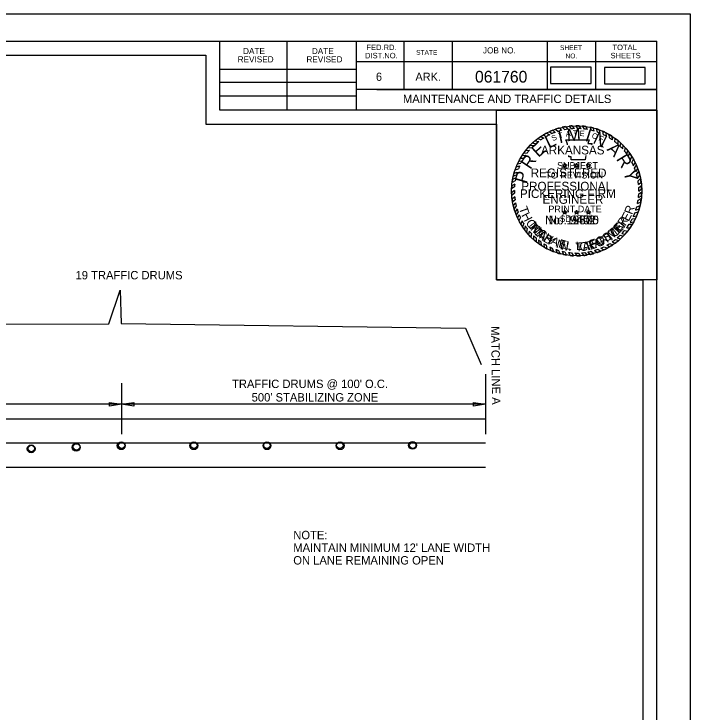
# Model space of a CAD drawing. Extents: x -500 to 213, y 382723 to 382830.
# Drawn here: x -198.06 to -149.61, y 382779.8 to 382829.8 of the extents above; entities that cross this region are included whole.
import ezdxf

# ---------------------------------------------------------------- set-up
doc = ezdxf.new("R2010")
doc.units = 0
for name, color, linetype in [('Default', 7, 'Continuous'), ('R_Border', 7, 'Continuous'), ('R_Border Notes', 7, 'Continuous'), ('R_No Plot', 7, 'Continuous'), ('STAMP_PE_CRAFTON', 7, 'Continuous'), ('STAMP_PE_FOSTER', 7, 'Continuous'), ('STAMP_PE_SEAL-INFO', 7, 'Continuous'), ('STAMP_PE_TAEGTMEYER', 7, 'Continuous'), ('STAMP_PE_TXT', 7, 'Continuous'), ('STAMP_PRELIMINARY', 7, 'Continuous')]:
    doc.layers.add(name, color=color, linetype=linetype)

msp = doc.modelspace()

# ---------------------------------------------------------------- linework, layer by layer
at = {"layer": 'Default'}
for p, q in [((-164.267, 382804.001), (-164.267, 382799.695)), ((-190.345, 382803.352), (-190.345, 382799.695)), ((-191.214, 382801.718), (-191.214, 382801.979)), ((-191.214, 382801.979), (-190.345, 382801.848)), ((-190.345, 382801.848), (-189.476, 382801.979)), ((-189.476, 382801.979), (-189.476, 382801.718)), ((-165.137, 382801.718), (-165.137, 382801.979)), ((-165.137, 382801.979), (-164.267, 382801.848)), ((-190.345, 382801.848), (-235.546, 382801.848)), ((-190.345, 382801.848), (-191.214, 382801.718)), ((-164.267, 382801.848), (-190.345, 382801.848)), ((-189.476, 382801.718), (-190.345, 382801.848)), ((-164.267, 382801.848), (-165.137, 382801.718)), ((-235.546, 382800.808), (-164.267, 382800.808)), ((-235.546, 382799.07), (-164.267, 382799.07)), ((-235.546, 382797.331), (-164.267, 382797.331))]:
    msp.add_line(p, q, dxfattribs=at)
for points in [[(-159.612, 382824.821), (-156.695, 382824.821), (-156.695, 382825.976), (-159.612, 382825.976)], [(-155.736, 382824.804), (-152.819, 382824.804), (-152.819, 382825.959), (-155.736, 382825.959)]]:
    msp.add_lwpolyline(points, close=True, dxfattribs=at)
msp.add_lwpolyline([(-235.059, 382804.933), (-233.084, 382807.551), (-191.258, 382807.599), (-190.452, 382810.018), (-190.38, 382807.634), (-165.711, 382807.3), (-164.57, 382804.702)], dxfattribs=at)
for centre, radius in [((-196.824, 382798.651), 0.281), ((-196.812, 382798.675), 0.229), ((-193.598, 382798.762), 0.281), ((-193.575, 382798.789), 0.229), ((-190.373, 382798.872), 0.281), ((-190.35, 382798.905), 0.229), ((-190.338, 382798.904), 0.229), ((-185.169, 382798.872), 0.281), ((-185.161, 382798.902), 0.229), ((-179.926, 382798.873), 0.281), ((-179.934, 382798.902), 0.229), ((-174.684, 382798.873), 0.281), ((-174.707, 382798.902), 0.229), ((-169.497, 382798.899), 0.281), ((-169.48, 382798.902), 0.229)]:
    msp.add_circle(centre, radius, dxfattribs=at)
at = {"layer": 'R_Border'}
for p, q in [((-310.08, 382827.85), (-151.99, 382827.85)), ((-183.31, 382822.91), (-183.31, 382827.85)), ((-178.47, 382822.91), (-178.47, 382827.85)), ((-173.54, 382827.85), (-173.54, 382822.91)), ((-170.12, 382827.85), (-170.12, 382824.38)), ((-166.65, 382827.85), (-166.65, 382824.38)), ((-159.86, 382827.85), (-159.86, 382824.38)), ((-156.39, 382827.85), (-156.39, 382824.38)), ((-151.99, 382725.12), (-151.99, 382827.85)), ((-151.99, 382826.38), (-173.54, 382826.38)), ((-151.99, 382826.39), (-151.99, 382826.39)), ((-183.31, 382825.84), (-173.54, 382825.84)), ((-183.31, 382824.91), (-173.54, 382824.91)), ((-151.99, 382824.38), (-173.54, 382824.38)), ((-172.06, 382824.38), (-151.99, 382824.38)), ((-183.31, 382823.94), (-173.54, 382823.94)), ((-151.99, 382822.91), (-183.31, 382822.91))]:
    msp.add_line(p, q, dxfattribs=at)
at = {"layer": 'R_No Plot'}
for points in [[(-316.283, 382829.798), (-149.613, 382829.798), (-149.613, 382723.129), (-316.283, 382723.129)], [(-152.99, 382777.485), (-309.08, 382777.485), (-309.08, 382826.85), (-184.31, 382826.85), (-184.31, 382821.91), (-175.54, 382821.91), (-163.49, 382821.91), (-163.49, 382810.744), (-152.99, 382810.744)], [(-309.08, 382826.85), (-184.31, 382826.85), (-184.31, 382821.91), (-175.54, 382821.91), (-163.49, 382821.91), (-163.49, 382810.744), (-152.99, 382810.744), (-152.99, 382726.12), (-309.08, 382726.12)], [(-163.49, 382822.91), (-151.99, 382822.91), (-151.99, 382810.744), (-163.49, 382810.744)]]:
    msp.add_lwpolyline(points, close=True, dxfattribs=at)
at = {"layer": 'STAMP_PE_SEAL-INFO'}
for p, q in [((-159.688, 382821.366), (-159.493, 382821.229)), ((-159.434, 382821.474), (-159.287, 382821.311)), ((-159.26, 382821.538), (-159.07, 382821.385)), ((-158.964, 382821.629), (-158.821, 382821.455)), ((-158.771, 382821.678), (-158.593, 382821.506)), ((-158.529, 382821.726), (-158.38, 382821.542)), ((-158.272, 382821.763), (-158.131, 382821.571)), ((-157.904, 382821.585), (-158.06, 382821.782)), ((-157.655, 382821.588), (-157.794, 382821.793)), ((-157.426, 382821.577), (-157.555, 382821.789)), ((-157.173, 382821.552), (-157.319, 382821.774)), ((-156.96, 382821.52), (-157.089, 382821.747)), ((-156.679, 382821.46), (-156.766, 382821.69)), ((-156.478, 382821.406), (-156.558, 382821.641)), ((-156.252, 382821.333), (-156.323, 382821.573)), ((-156.043, 382821.253), (-156.115, 382821.501)), ((-155.812, 382821.15), (-155.864, 382821.399)), ((-160.531, 382820.88), (-160.303, 382820.778)), ((-160.321, 382821.013), (-160.1, 382820.912)), ((-160.127, 382821.135), (-159.911, 382821.024)), ((-159.903, 382821.261), (-159.671, 382821.148)), ((-155.59, 382821.036), (-155.633, 382821.29)), ((-155.396, 382820.922), (-155.416, 382821.172)), ((-155.179, 382820.779), (-155.194, 382821.037)), ((-154.998, 382820.646), (-154.981, 382820.889)), ((-161.059, 382820.405), (-160.787, 382820.384)), ((-160.891, 382820.566), (-160.662, 382820.497)), ((-160.719, 382820.716), (-160.455, 382820.666)), ((-158.503, 382820.777), (-156.831, 382820.777)), ((-158.443, 382820.624), (-158.503, 382820.777)), ((-158.391, 382820.475), (-158.443, 382820.624)), ((-158.387, 382820.418), (-158.391, 382820.475)), ((-156.831, 382820.777), (-156.944, 382820.531)), ((-156.944, 382820.531), (-156.627, 382820.531)), ((-156.627, 382820.531), (-156.7, 382820.418)), ((-154.775, 382820.459), (-154.765, 382820.721)), ((-154.619, 382820.313), (-154.584, 382820.563)), ((-154.439, 382820.127), (-154.406, 382820.39)), ((-161.393, 382820.027), (-161.119, 382820.038)), ((-161.22, 382820.232), (-160.959, 382820.213)), ((-154.302, 382819.968), (-154.234, 382820.204)), ((-154.14, 382819.76), (-154.073, 382820.01)), ((-161.772, 382819.469), (-161.528, 382819.48)), ((-161.649, 382819.67), (-161.391, 382819.687)), ((-161.532, 382819.842), (-161.28, 382819.839)), ((-158.291, 382819.563), (-158.304, 382819.672)), ((-158.134, 382819.563), (-158.291, 382819.563)), ((-158.134, 382819.348), (-158.134, 382819.563)), ((-157.112, 382819.517), (-157.119, 382819.348)), ((-157.073, 382819.672), (-157.112, 382819.517)), ((-154.03, 382819.602), (-153.941, 382819.834)), ((-153.876, 382819.354), (-153.785, 382819.599)), ((-153.777, 382819.17), (-153.663, 382819.392)), ((-162.074, 382818.847), (-161.822, 382818.92)), ((-161.982, 382819.063), (-161.731, 382819.115)), ((-161.888, 382819.258), (-161.639, 382819.29)), ((-157.119, 382819.348), (-158.134, 382819.348)), ((-153.661, 382818.928), (-153.548, 382819.171)), ((-153.591, 382818.76), (-153.459, 382818.977)), ((-162.227, 382818.393), (-161.989, 382818.477)), ((-162.149, 382818.644), (-161.907, 382818.712)), ((-153.493, 382818.485), (-153.358, 382818.722)), ((-153.44, 382818.303), (-153.293, 382818.529)), ((-162.097, 382818.066), (-162.33, 382817.941)), ((-162.28, 382818.189), (-162.045, 382818.285)), ((-153.373, 382818.024), (-153.214, 382818.247)), ((-153.339, 382817.834), (-153.162, 382818.01)), ((-162.188, 382817.406), (-162.399, 382817.278)), ((-162.17, 382817.618), (-162.388, 382817.478)), ((-162.14, 382817.836), (-162.363, 382817.725)), ((-153.305, 382817.579), (-153.119, 382817.747)), ((-153.289, 382817.37), (-153.094, 382817.516)), ((-162.196, 382817.159), (-162.399, 382816.991)), ((-162.193, 382816.956), (-162.389, 382816.793)), ((-153.289, 382816.908), (-153.079, 382817.047)), ((-153.283, 382817.111), (-153.08, 382817.272)), ((-162.176, 382816.708), (-162.362, 382816.53)), ((-162.15, 382816.493), (-162.327, 382816.307)), ((-153.334, 382816.461), (-153.112, 382816.571)), ((-153.308, 382816.655), (-153.091, 382816.783)), ((-162.111, 382816.264), (-162.281, 382816.08)), ((-162.064, 382816.055), (-162.221, 382815.847)), ((-153.433, 382815.985), (-153.197, 382816.086)), ((-153.379, 382816.211), (-153.152, 382816.309)), ((-162.002, 382815.831), (-162.15, 382815.622)), ((-161.932, 382815.619), (-162.073, 382815.414)), ((-161.849, 382815.406), (-161.98, 382815.195)), ((-153.574, 382815.548), (-153.332, 382815.614)), ((-153.506, 382815.738), (-153.261, 382815.838)), ((-161.763, 382815.214), (-161.877, 382814.984)), ((-161.646, 382814.985), (-161.741, 382814.74)), ((-153.897, 382814.873), (-153.647, 382814.901)), ((-153.761, 382815.123), (-153.517, 382815.157)), ((-153.681, 382815.291), (-153.437, 382815.339)), ((-161.528, 382814.784), (-161.62, 382814.548)), ((-161.426, 382814.628), (-161.481, 382814.352)), ((-161.286, 382814.433), (-161.337, 382814.167)), ((-154.153, 382814.486), (-153.901, 382814.488)), ((-153.983, 382814.733), (-153.745, 382814.73)), ((-161.134, 382814.244), (-161.177, 382813.984)), ((-160.983, 382814.075), (-161.014, 382813.814)), ((-160.822, 382813.912), (-160.837, 382813.648)), ((-154.626, 382813.943), (-154.406, 382813.874)), ((-154.499, 382814.073), (-154.26, 382814.03)), ((-154.307, 382814.289), (-154.076, 382814.249)), ((-160.649, 382813.756), (-160.651, 382813.491)), ((-160.469, 382813.609), (-160.46, 382813.347)), ((-160.3, 382813.484), (-160.282, 382813.225)), ((-155.367, 382813.359), (-155.142, 382813.261)), ((-155.195, 382813.473), (-154.975, 382813.378)), ((-154.964, 382813.645), (-154.73, 382813.572)), ((-154.829, 382813.757), (-154.593, 382813.692)), ((-160.087, 382813.343), (-160.056, 382813.087)), ((-159.912, 382813.24), (-159.866, 382812.984)), ((-159.671, 382813.115), (-159.593, 382812.855)), ((-159.485, 382813.031), (-159.398, 382812.775)), ((-159.238, 382812.935), (-159.134, 382812.684)), ((-159.034, 382812.867), (-158.921, 382812.622)), ((-156.463, 382812.862), (-156.255, 382812.713)), ((-156.217, 382812.943), (-155.996, 382812.809)), ((-156.007, 382813.025), (-155.796, 382812.895)), ((-155.778, 382813.13), (-155.536, 382813.024)), ((-155.574, 382813.237), (-155.365, 382813.12)), ((-158.78, 382812.798), (-158.674, 382812.565)), ((-158.581, 382812.755), (-158.458, 382812.526)), ((-158.331, 382812.714), (-158.211, 382812.494)), ((-158.113, 382812.691), (-157.975, 382812.476)), ((-157.87, 382812.677), (-157.719, 382812.47)), ((-157.64, 382812.676), (-157.468, 382812.478)), ((-157.381, 382812.689), (-157.218, 382812.5)), ((-157.162, 382812.713), (-156.975, 382812.533)), ((-156.939, 382812.747), (-156.745, 382812.578)), ((-156.693, 382812.8), (-156.504, 382812.637))]:
    msp.add_line(p, q, dxfattribs=at)
for radius, start, end in [(4.661, 111.3124, 114.7026), (4.661, 105.2339, 109.0352), (4.457, 104.0352, 107.3615), (4.661, 99.7525, 102.7765), (4.457, 98.258, 101.0329), (4.661, 93.9381, 96.5517), (4.457, 92.1102, 95.0367), (4.661, 87.7298, 90.6707), (4.457, 85.9628, 88.9097), (4.661, 81.9732, 84.8236), (4.457, 79.9264, 82.696), (4.661, 75.3125, 77.9426), (4.457, 73.5575, 76.2314), (4.661, 69.6061, 72.3058), (4.661, 63.1329, 66.2704), (4.661, 123.6199, 126.5906), (4.457, 121.9746, 125.11), (4.661, 117.6544, 120.8099), (4.457, 115.6869, 119.1583), (4.457, 110.3086, 113.1659), (4.457, 67.6248, 70.504), (4.457, 61.1558, 64.3784), (4.661, 56.9003, 60.0942), (4.457, 54.9238, 58.2702), (4.661, 50.3492, 53.7159), (4.661, 135.4021, 138.3031), (4.457, 133.1331, 136.2562), (4.661, 129.7326, 132.5376), (4.457, 127.5297, 130.9683), (4.457, 48.3016, 52.0395), (4.661, 44.3405, 47.3929), (4.661, 141.6056, 144.4486), (4.457, 139.301, 142.5873), (4.457, 42.2212, 45.5512), (4.457, 36.135, 39.5311), (4.661, 38.1247, 41.2316), (4.661, 147.0072, 149.899), (4.457, 145.0197, 148.2104), (4.457, 29.9032, 33.6645), (4.661, 31.9614, 35.4294), (4.661, 25.9391, 29.0125), (4.661, 152.864, 155.5189), (4.457, 156.3402, 159.2319), (4.457, 151.0315, 153.573), (4.457, 23.7732, 27.2211), (4.661, 19.9538, 23.3141), (4.661, 164.3068, 166.894), (4.661, 158.4077, 161.0701), (4.457, 162.4331, 165.0013), (4.457, 17.6802, 21.4251), (4.661, 13.8421, 17.4447), (4.661, 170.0003, 172.6878), (4.457, 167.9048, 170.9039), (4.457, 11.5444, 15.2364), (4.661, 7.5852, 10.8621), (4.661, 175.7409, 178.2066), (4.457, 173.73, 176.4734), (4.457, 5.7599, 9.0606), (4.457, 359.7329, 3.0639), (4.661, 1.7215, 4.7268), (4.661, 181.7251, 184.1626), (4.457, 179.6454, 182.2633), (4.457, 353.8632, 357.1274), (4.661, 355.7156, 358.9569), (4.661, 187.4204, 190.1927), (4.457, 185.4539, 188.234), (4.457, 348.0778, 351.3435), (4.661, 349.8305, 353.0885), (4.661, 193.0369, 195.9973), (4.457, 191.2274, 193.9858), (4.457, 341.777, 345.0925), (4.661, 343.8925, 347.035), (4.661, 198.8967, 201.6281), (4.457, 196.9675, 199.8353), (4.457, 202.7761, 205.4791), (4.457, 335.6038, 339.1858), (4.661, 337.3837, 340.9933), (4.661, 204.5479, 207.4328), (4.457, 208.7883, 211.7934), (4.457, 329.5549, 333.2076), (4.661, 331.4037, 334.9332), (4.661, 210.8636, 213.6571), (4.661, 216.6115, 219.491), (4.457, 214.1838, 217.2747), (4.457, 323.5851, 327.4407), (4.661, 325.4405, 328.9872), (4.661, 222.48, 225.3801), (4.457, 220.3909, 223.3056), (4.457, 226.2494, 229.2407), (4.457, 310.7744, 314.3161), (4.661, 312.4518, 315.6633), (4.457, 316.6531, 320.3711), (4.661, 318.2846, 321.8043), (4.661, 228.3665, 231.348), (4.457, 232.229, 234.9336), (4.457, 299.0768, 302.1724), (4.457, 304.823, 308.5143), (4.661, 306.3721, 310.208), (4.661, 234.295, 236.9452), (4.457, 238.2223, 240.8353), (4.661, 240.1977, 242.8613), (4.457, 244.3204, 246.9486), (4.661, 246.576, 249.1558), (4.457, 250.3491, 253.1216), (4.457, 286.6423, 289.9783), (4.457, 292.8745, 296.1185), (4.661, 294.6481, 298.2166), (4.661, 300.621, 303.8703), (4.661, 252.5967, 255.3252), (4.457, 256.505, 259.1192), (4.661, 258.4433, 261.1398), (4.457, 262.3783, 265.2012), (4.661, 264.1978, 267.1009), (4.457, 268.3215, 271.277), (4.661, 270.2548, 273.3361), (4.457, 274.6157, 277.4486), (4.661, 276.4239, 279.4357), (4.457, 280.3459, 283.5814), (4.661, 282.3199, 285.3702), (4.661, 288.5709, 291.9733)]:
    msp.add_arc((-157.74, 382817.132), radius, start, end, dxfattribs=at)
at = {"layer": 'STAMP_PE_TXT'}
for p, q in [((-158.65, 382818.917), (-158.749, 382818.99)), ((-158.749, 382818.99), (-158.627, 382818.99)), ((-158.688, 382818.801), (-158.65, 382818.917)), ((-158.589, 382818.873), (-158.688, 382818.801)), ((-158.627, 382818.99), (-158.589, 382819.106)), ((-158.589, 382819.106), (-158.551, 382818.99)), ((-158.489, 382818.801), (-158.589, 382818.873)), ((-158.551, 382818.99), (-158.428, 382818.99)), ((-158.428, 382818.99), (-158.527, 382818.917)), ((-158.527, 382818.917), (-158.489, 382818.801)), ((-157.801, 382818.917), (-157.9, 382818.99)), ((-157.9, 382818.99), (-157.778, 382818.99)), ((-157.839, 382818.801), (-157.801, 382818.917)), ((-157.74, 382818.873), (-157.839, 382818.801)), ((-157.778, 382818.99), (-157.74, 382819.106)), ((-157.74, 382819.106), (-157.702, 382818.99)), ((-157.64, 382818.801), (-157.74, 382818.873)), ((-157.702, 382818.99), (-157.579, 382818.99)), ((-157.579, 382818.99), (-157.678, 382818.917)), ((-157.678, 382818.917), (-157.64, 382818.801)), ((-156.952, 382818.917), (-157.051, 382818.99)), ((-157.051, 382818.99), (-156.929, 382818.99)), ((-156.99, 382818.801), (-156.952, 382818.917)), ((-156.891, 382818.873), (-156.99, 382818.801)), ((-156.929, 382818.99), (-156.891, 382819.106)), ((-156.891, 382819.106), (-156.853, 382818.99)), ((-156.792, 382818.801), (-156.891, 382818.873)), ((-156.853, 382818.99), (-156.73, 382818.99)), ((-156.73, 382818.99), (-156.829, 382818.917)), ((-156.829, 382818.917), (-156.792, 382818.801)), ((-158.65, 382815.564), (-158.749, 382815.636)), ((-158.749, 382815.636), (-158.627, 382815.636)), ((-158.688, 382815.447), (-158.65, 382815.564)), ((-158.589, 382815.519), (-158.688, 382815.447)), ((-158.627, 382815.636), (-158.589, 382815.753)), ((-158.589, 382815.753), (-158.551, 382815.636)), ((-158.489, 382815.447), (-158.589, 382815.519)), ((-158.551, 382815.636), (-158.428, 382815.636)), ((-158.428, 382815.636), (-158.527, 382815.564)), ((-158.527, 382815.564), (-158.489, 382815.447)), ((-157.801, 382815.564), (-157.9, 382815.636)), ((-157.9, 382815.636), (-157.778, 382815.636)), ((-157.839, 382815.447), (-157.801, 382815.564)), ((-157.74, 382815.519), (-157.839, 382815.447)), ((-157.778, 382815.636), (-157.74, 382815.753)), ((-157.74, 382815.753), (-157.702, 382815.636)), ((-157.64, 382815.447), (-157.74, 382815.519)), ((-157.702, 382815.636), (-157.579, 382815.636)), ((-157.579, 382815.636), (-157.678, 382815.564)), ((-157.678, 382815.564), (-157.64, 382815.447)), ((-156.952, 382815.564), (-157.051, 382815.636)), ((-157.051, 382815.636), (-156.929, 382815.636)), ((-156.99, 382815.447), (-156.952, 382815.564)), ((-156.891, 382815.519), (-156.99, 382815.447)), ((-156.929, 382815.636), (-156.891, 382815.753)), ((-156.891, 382815.753), (-156.853, 382815.636)), ((-156.792, 382815.447), (-156.891, 382815.519)), ((-156.853, 382815.636), (-156.73, 382815.636)), ((-156.73, 382815.636), (-156.829, 382815.564)), ((-156.829, 382815.564), (-156.792, 382815.447))]:
    msp.add_line(p, q, dxfattribs=at)
at = {"layer": 'STAMP_PRELIMINARY'}
msp.add_circle((-157.74, 382817.132), 4.661, dxfattribs=at)

# ---------------------------------------------------------------- texts
at = {"layer": 'Default'}
for s, p in [('19 TRAFFIC DRUMS', (-193.644, 382810.789)), ("TRAFFIC DRUMS @ 100' O.C.", (-182.431, 382803.004)), ("500' STABILIZING ZONE", (-181.027, 382802.04)), ('NOTE:', (-178.043, 382792.175)), ("MAINTAIN MINIMUM 12' LANE WIDTH", (-178.043, 382791.27)), ('ON LANE REMAINING OPEN', (-178.043, 382790.365))]:
    msp.add_text(s, height=0.6, dxfattribs=at).set_placement(p)
msp.add_text('MATCH LINE A', height=0.6, rotation=270.8059, dxfattribs=at).set_placement((-163.875, 382807.429))
at = {"layer": 'R_Border'}
for s, height, p in [('DATE', 0.4396, (-181.641, 382826.919)), ('DATE', 0.4396, (-176.711, 382826.919)), ('FED.RD.', 0.391, (-172.8, 382827.21)), ('JOB NO.', 0.4396, (-164.45, 382826.97)), ('SHEET', 0.342, (-158.93, 382827.21)), ('TOTAL', 0.391, (-155.17, 382827.21)), ('DIST.NO.', 0.391, (-172.9, 382826.62)), ('STATE', 0.342, (-169.24, 382826.87)), ('NO.', 0.342, (-158.54, 382826.62)), ('SHEETS', 0.391, (-155.31, 382826.62)), ('REVISED', 0.4396, (-182.031, 382826.329)), ('REVISED', 0.4396, (-177.101, 382826.329)), ('6', 0.586, (-172.12, 382825.01)), ('ARK.', 0.5861, (-169.29, 382825.01))]:
    msp.add_text(s, height=height, dxfattribs=at).set_placement(p)
at = {"layer": 'R_Border Notes'}
for s, height, p in [('061760', 0.84, (-165.021, 382824.883)), ('MAINTENANCE AND TRAFFIC DETAILS', 0.6, (-170.186, 382823.42))]:
    msp.add_text(s, height=height, dxfattribs=at).set_placement(p)
at = {"layer": 'STAMP_PE_CRAFTON'}
msp.add_text('No. 12370', height=0.625, dxfattribs=at).set_placement((-160.009, 382814.73))
for s, rotation, p in [('T', 310.7442, (-161.257, 382814.581)), ('N', 49.2411, (-154.598, 382814.143)), ('O', 317.6422, (-160.923, 382814.175)), ('O', 41.8391, (-155.022, 382813.752)), ('N', 324.4537, (-160.5, 382813.783)), ('Y', 331.1686, (-159.984, 382813.424)), ('F', 28.7821, (-155.909, 382813.196)), ('T', 34.1136, (-155.451, 382813.451)), ('N', 347.4752, (-158.956, 382812.966)), ('C', 6.0117, (-157.504, 382812.802)), ('R', 14.8189, (-156.956, 382812.86)), ('A', 20.5125, (-156.399, 382813.01)), ('.', 356.8926, (-158.342, 382812.828))]:
    msp.add_text(s, height=0.625, rotation=rotation, dxfattribs=at).set_placement(p)
at = {"layer": 'STAMP_PE_FOSTER'}
msp.add_text('No. 9402', height=0.625, dxfattribs=at).set_placement((-159.747, 382814.73))
for s, rotation, p in [('M', 308.339, (-161.182, 382814.643)), ('E', 46.9613, (-154.739, 382814.127)), ('R', 54.5031, (-154.378, 382814.537)), ('I', 314.1842, (-160.783, 382814.174)), ('T', 39.4194, (-155.169, 382813.752)), ('C', 319.8733, (-160.606, 382813.997)), ('H', 327.7235, (-160.141, 382813.629)), ('O', 23.719, (-156.2, 382813.173)), ('S', 31.7234, (-155.644, 382813.438)), ('A', 335.7276, (-159.651, 382813.338)), ('E', 343.5779, (-159.082, 382813.103)), ('L', 350.8115, (-158.553, 382812.964)), ('L', 1.2666, (-157.783, 382812.886)), ('F', 15.8691, (-156.722, 382813.009)), ('.', 6.8035, (-157.26, 382812.915))]:
    msp.add_text(s, height=0.6, rotation=rotation, dxfattribs=at).set_placement(p)
at = {"layer": 'STAMP_PE_TAEGTMEYER'}
for s, rotation, p in [('T', 289.646, (-161.892, 382815.887)), ('R', 69.57, (-153.767, 382815.389)), ('H', 296.7339, (-161.713, 382815.395)), ('E', 63.0984, (-154.016, 382814.898)), ('O', 303.7708, (-161.416, 382814.841)), ('Y', 53.9986, (-154.351, 382814.428)), ('M', 314.2033, (-161.089, 382814.365)), ('M', 39.3, (-155.241, 382813.581)), ('E', 46.8094, (-154.72, 382814.02)), ('A', 321.0594, (-160.608, 382813.883)), ('S', 327.8239, (-160.195, 382813.561)), ('T', 31.466, (-155.69, 382813.309)), ('N', 344.2727, (-159.246, 382813.058)), ('T', 3.0061, (-157.808, 382812.792)), ('A', 8.9826, (-157.284, 382812.82)), ('E', 17.6836, (-156.765, 382812.897)), ('G', 23.3052, (-156.24, 382813.063)), ('.', 350.6464, (-158.64, 382812.892))]:
    msp.add_text(s, height=0.625, rotation=rotation, dxfattribs=at).set_placement(p)
msp.add_text('No. 19605', height=0.625, dxfattribs=at).set_placement((-160.009, 382814.73))
at = {"layer": 'STAMP_PE_TXT'}
for s, rotation, p in [('A', 9.0679, (-158.498, 382820.996)), ('T', 1.8248, (-158.004, 382821.061)), ('E', 355.2002, (-157.549, 382821.065)), ('S', 23.5541, (-159.44, 382820.684)), ('T', 16.311, (-158.979, 382820.87)), ('O', 342.2506, (-156.686, 382820.927)), ('F', 335.0075, (-156.203, 382820.758))]:
    msp.add_text(s, height=0.391, rotation=rotation, dxfattribs=at).set_placement(p)
for s, p in [('ARKANSAS', (-160.294, 382819.737)), ('REGISTERED', (-161.031, 382818.102)), ('PROFESSIONAL', (-161.705, 382817.151)), ('ENGINEER', (-160.185, 382816.201))]:
    msp.add_text(s, height=0.625, dxfattribs=at).set_placement(p)
at = {"layer": 'STAMP_PRELIMINARY'}
for s, rotation, p in [('I', 12.5248, (-158.971, 382820.525)), ('M', 3.1074, (-158.422, 382820.68)), ('I', 342.3164, (-157.188, 382820.713)), ('L', 25.513, (-159.735, 382820.145)), ('N', 333.9382, (-156.634, 382820.576)), ('E', 42.3578, (-160.477, 382819.48)), ('A', 315.6579, (-155.617, 382820.064)), ('R', 56.2292, (-161.054, 382818.614)), ('R', 301.3831, (-154.933, 382819.407)), ('P', 73.913, (-161.329, 382817.602)), ('Y', 283.2593, (-154.389, 382818.513))]:
    msp.add_text(s, height=0.9, rotation=rotation, dxfattribs=at).set_placement(p)
for s, height, p in [('SUBJECT', 0.48, (-159.14, 382818.706)), ('TO REVISION', 0.48, (-159.972, 382818.014)), ('PICKERING FIRM', 0.625, (-161.803, 382816.613)), ('PRINT DATE', 0.48, (-159.761, 382815.589)), ('$DATE$', 0.48, (-158.923, 382814.897))]:
    msp.add_text(s, height=height, dxfattribs=at).set_placement(p)

doc.saveas('drawing.dxf')
